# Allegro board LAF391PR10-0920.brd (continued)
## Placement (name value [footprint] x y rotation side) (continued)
PR1240  100K_0402_1%  [R_0402]  56.48 69.47 0 top
PR1241  0_0402_5%  [R0402_0OHM]  44.53 52.02 180 top
PR1242  0_0402_5%  [R0402_0OHM]  48.07 58.22 180 top
PR1243  0_0402_5%  [R0402_0OHM]  57.36 70.34 0 top
PR1244  0_0402_5%  [R0402_0OHM]  50.48 52.99 180 top
PR1245  0_0402_5%  [R0402_0OHM]  40.75 57.83 90 top
PR1246  100K_0402_1%  [R_0402]  53.54 74.39 180 top
PR1247  100K_0402_1%  [R_0402]  55.67 70.34 180 top
PR1248  0_0402_5%  [R_0402]  49.92 71.42 180 top
PR1249  10K_0402_5%  [R_0402]  49.23 73.18 180 top
PR1250  0_0402_5%  [R0402_0OHM]  49.92 72.3 180 top
PR1251  300K_0402_5%  [R_0402]  41.58 72.37 0 top
PR1252  100K_0402_5%  [R_0402]  43.34 72.38 0 top
PR1253  100K_0402_5%  [R_0402]  41.82 78.12 270 top
PR1254  0_0402_5%  [R_0402]  51.52 51.91 270 top
PR1255  150K_0402_1%  [R_0402]  50.87 76.46 0 top
PR1257  0_0402_5%  [R0402_0OHM]  48.07 55.62 180 top
PR1258  0_0402_5%  [R_0402]  48.07 59.1 180 top
PR1259  100K_0402_5%  [R_0402]  49.54 50.93 0 top
PR1260  0_0402_5%  [R_0402]  50.47 52.12 180 top
PR1261  0_0402_5%  [R_0402]  48.07 53.83 180 top
PR1262  100K_0402_5%  [R_0402]  38.75 72.35 90 top
PRP1  100_0804_8P4R_5%  [RP_0804_8P4R]  34.64 19.22 90 top
PT1  PAD~D  [TPC12]  48.05 71.62 0 top
PU1  MC74VHC1G08DFT2G_SC70-5P  [TC7SH08FU_SSOP5]  52.49 88.55 180 bottom
PU2  RT9058-33GX SOT-89 3P LDO  [AP2204R-5P0TRG1_SOT89-3]  52.74 77.67 0 bottom
PU100  -  [SY8288BRAC_QFN20_3X3]  142.03 108.15 270 bottom
PU102  SYV828CRAC QFN 20P PWM  [SY8288CRAC_QFN20_3X3]  43.42 45.54 180 bottom
PU200  -  [SY8210AQVC_QFN19_4X3]  57.23 58.35 90 bottom
PU301  SY8286RAC_QFN20_3X3  [SY8288RAC_QFN20_3X3]  159.22 104.32 0 bottom
PU401  TPS62134CRGT_QFN16_3X3  [SY8057QDC_QFN16_3X3]  173.67 49.7 0 bottom
PU402  TPS62134DRGT_QFN16_3X3  [SY8057QDC_QFN16_3X3]  171.15 98.87 0 bottom
PU501  RT8097ALGE SOT23 6P PWM  [RT8097ALGE_SOT23-6]  173.71 106.15 90 bottom
PU503  AP7361C-FGE-7-01_U-DFN3030-8_3X3  [AP7361C-FGE-7_U-DFN3030-8_3X3]  216.69 14.2 270 top
PU602  ISL95857AHRTZ-T TQFN 40P PWM  [ISL62883CHRTZ-T_TQFN40_5X5-S]  66.57 64.53 0 top
PU610  FDMF3035_PQFN31_5X5  [FDMF3035_PQFN31_5X5-S]  83.71 58.54 180 bottom
PU612  FDMF3035_PQFN31_5X5  [FDMF3035_PQFN31_5X5-S]  64.28 49.41 90 bottom
PU613  FDMF3035_PQFN31_5X5  [FDMF3035_PQFN31_5X5-S]  73.51 76.23 90 bottom
PU614  S IC ISL95808HRZ-TS2778 DFN MOSFET DRIVE  [ISL95808HRZ-TS2378_DFN8_2X2-S]  86.86 87.14 0 bottom
PU901  ISL9538HRTZ-TS2778 TQFN 32P CHARGER  [ISL88738HRTZ-T_TQFN32_4X4]  33.1 45.44 180 bottom
PU903  MC74VHC1G08DFT2G SC70 5P  [TC7SH08FU_SSOP5]  26.98 50.07 270 top
PU1200  MC74VHC1G08DFT2G SC70 5P  [TC7SH08FU_SSOP5]  39.37 76.19 180 top
PU1201  -  [LM393DGKR_VSSOP8]  58.31 77.19 270 top
QC2  -  [DMN65D8LDW-7_SOT363-6]  157.71 66.03 90 top
QC6  -  [L2N7002WT1G_SC-70-3]  246.56 41.7 90 top
QC7  -  [LP2301ALT1G_SOT23-3]  249.69 46.53 180 top
QE2  -  [DMN65D8LDW-7_SOT363-6]  248.34 50.03 270 top
QE3  -  [MMST3904-7-F_SOT323-3]  105.53 58.28 270 top
QE4  -  [MMST3904-7-F_SOT323-3]  105.21 92.92 0 bottom
QE5  -  [MMST3904-7-F_SOT323-3]  210.63 28.76 180 top
QE6  -  [MMST3904-7-F_SOT323-3]  93.07 80.48 270 bottom
QE7  -  [MMST3904-7-F_SOT323-3]  125.99 26.27 270 bottom
QE11  -  [L2N7002WT1G_SC-70-3]  109.66 90.91 180 bottom
QE12  -  [L2N7002WT1G_SC-70-3]  264.16 62.08 0 top
QE15  -  [LP2301ALT1G_SOT23-3]  279.07 66.47 180 top
QE17  -  [L2N7002WT1G_SC-70-3]  259.01 64.12 0 top
QL1  -  [DMN65D8LDW-7_SOT363-6]  270.63 64.57 90 top
QL2  -  [DMN65D8LDW-7_SOT363-6]  270.63 67.43 90 top
QN1  -  [DMN65D8LDW-7_SOT363-6]  249.48 14.78 0 top
QN4  DMN65D8LDW-7_SOT363-6  [DMN66D0LDW-7_SOT363-6]  223.32 33.96 270 top
QN5  DMN65D8LDW-7_SOT363-6  [DMN66D0LDW-7_SOT363-6]  232.58 27.8 0 top
QN6  -  [L2N7002WT1G_SC-70-3]  221.37 30.64 0 top
QN7  -  [L2N7002WT1G_SC-70-3]  218.88 30.65 0 top
QR1  -  [L2N7002WT1G_SC-70-3]  89.97 91.23 180 top
QT1  -  [DMN66D0LDW-7_SOT363-6]  36.15 65.39 270 top
QV1  -  [AO6405_TSOP6]  75.05 98.64 0 top
QV2  -  [L2N7002WT1G_SC-70-3]  77.27 95.74 90 top
QV3  -  [DMN65D8LDW-7_SOT363-6]  20.88 50.21 90 bottom
QV4  -  [L2N7002WT1G_SC-70-3]  19.99 50.41 180 top
QV5  -  [L2N7002WT1G_SC-70-3]  16.31 51.55 180 top
QV7  -  [L2N7002WT1G_SC-70-3]  71.63 108.68 90 top
QV8  -  [LP2301ALT1G_SOT23-3]  65.8 108.92 270 top
QZ1  -  [LP2301ALT1G_SOT23-3]  65.61 96.44 90 top
QZ2  -  [DMN65D8LDW-7_SOT363-6]  282.88 37.31 90 top
QZ3  DDTA114EUA-7-F_SOT323-3  [DDTA144VCA-7-F_SOT23-3]  267.14 29.18 0 top
QZ4  -  [L2N7002WT1G_SC-70-3]  243.64 46.09 180 top
QZ7  -  [DMN65D8LDW-7_SOT363-6]  277.37 70.4 180 top
QZ15  S TR BSS138W 1N SOT-323-3  [L2N7002WT1G_SC-70-3]  223.39 35.75 270 top
R274  0_0603_5%  [R0603_0OHM]  82.92 93.01 0 top
RA3  0_0603_5%  [R0603_0OHM]  265.36 12.75 90 top
RA5  2.2K_0402_5%  [R_0402]  270.54 16.73 0 top
RA6  2.2K_0402_5%  [R_0402]  270.54 17.6 0 top
RA7  16.2_0402_1%  [R_0402]  271.45 15.87 180 top
RA8  16.2_0402_1%  [R_0402]  271.05 14.65 180 top
RA9  33_0402_5%  [R_0402]  261.03 15.6 0 top
RA12  1K_0402_5%  [R_0402]  273.58 22.35 90 top
RA13  1K_0402_5%  [R_0402]  273.58 25.4 270 top
RA14  22_0402_5%  [R_0402]  259.72 19.88 0 top
RA17  33_0402_5%  [R_0402]  254.92 18.31 0 top
RA18  10K_0402_5%  [R_0402]  255.07 24.51 270 top
RA35  0_0402_5%  [R0402_0OHM]  273.61 26.23 90 top
RA36  0_0402_5%  [R0402_0OHM]  276.99 11.98 180 top
RA37  0_0402_5%  [R0402_0OHM]  276.85 19.33 0 bottom
RA44  100K_0402_5%  [R_0402]  272.17 22.84 180 top
RA45  10K_0402_5%  [R_0402]  276.28 21.54 270 top
RA48  0_0402_5%  [R0402_0OHM]  257.36 24.63 270 top
RA50  0_0402_5%  [R_0402]  257.36 21.94 90 top
RA51  10K_0402_5%  [R_0402]  273.61 21.54 270 top
RA53  0_0402_5%  [R_0402]  262.69 25.8 90 bottom
RA57  0_0402_5%  [R0402_0OHM]  263.55 25.8 90 bottom
RA58  10K_0402_5%  [R_0402]  253.8 13.28 0 bottom
RA59  100K_0402_1%  [R_0402]  255.38 26.97 0 top
RA60  200K_0402_1%  [R_0402]  259.14 24.13 180 top
RA61  100K_0402_1%  [R_0402]  265.38 25.8 90 bottom
RA62  100K_0402_5%  [R_0402]  257.22 20.71 0 top
RC1  100K_0402_5%  [R_0402]  134.97 66.8 270 top
RC2  24.9_0402_1%  [R_0402]  111 81.07 180 top
RC3  100_0402_1%  [R_0402]  140.52 80.18 180 top
RC4  200_0402_1%  [R_0402]  151.21 54.36 0 bottom
RC5  121_0402_1%  [R_0402]  129.44 57.01 90 top
RC6  80.6_0402_1%  [R_0402]  128.96 44.5 270 top
RC7  100_0402_1%  [R_0402]  129.98 44.5 270 top
RC10  1K_0402_1%  [R_0402]  162.23 46.97 270 top
RC11  1K_0402_1%  [R_0402]  167.19 49.58 270 bottom
RC12  1K_0402_5%  [R_0402]  147.14 64.45 270 top
RC14  1K_0402_5%  [R_0402]  146.28 64.45 270 top
RC15  1K_0402_5%  [R_0402]  150.36 65.49 90 bottom
RC16  15_0402_5%  [R_0402]  142.3 44.07 0 top
RC17  1K_0402_5%  [R_0402]  148.47 66.43 0 bottom
RC19  499_0402_1%  [R_0402]  155.25 62.92 90 bottom
RC20  499_0402_1%  [R_0402]  154.21 65.55 0 bottom
RC21  8.2K_0402_1%  [R_0402]  154.8 47.35 90 top
RC22  22_0402_5%  [R_0402]  144.07 44.07 0 top
RC23  2.2K_0402_5%  [R_0402]  136.08 64.54 270 top
RC25  4.7K_0402_5%  [R_0402]  151.25 65.49 90 bottom
RC27  8.2K_0402_5%  [R_0402]  140 39.22 180 top
RC28  33_0402_5%  [R_0402]  161.68 49.34 180 bottom
RC29  33_0402_5%  [R_0402]  163.26 52.29 270 bottom
RC30  1K_0402_5%  [R_0402]  168.46 60.37 270 bottom
RC31  1K_0402_5%  [R_0402]  163.63 48.69 90 bottom
RC32  0_0402_5%  [R_0402]  165.67 66.73 325 bottom
RC33  0_0402_5%  [R0402_0OHM]  165.92 65.32 325 bottom
RC34  0_0402_5%  [R0402_0OHM]  167.7 65.33 325 bottom
RC35  0_0402_5%  [R0402_0OHM]  168.08 63.8 325 bottom
RC36  0_0402_5%  [R0402_0OHM]  169.48 64.19 325 bottom
RC37  0_0402_5%  [R0402_0OHM]  159.94 63.28 270 bottom
RC38  0_0402_5%  [R0402_0OHM]  169.99 62.54 325 bottom
RC39  33_0402_5%  [R_0402]  167.57 59.61 180 bottom
RC40  0_0402_5%  [R0402_0OHM]  171.38 62.92 325 bottom
RC41  0_0402_5%  [R0402_0OHM]  173.66 61.25 145 bottom
RC42  0_0402_5%  [R_0402]  160.49 66.09 180 bottom
RC43  33_0402_5%  [R_0402]  167.57 58.72 180 bottom
RC44  113_0402_1%  [R_0402]  149.38 65.53 270 top
RC45  100_0402_1%  [R_0402]  140.9 77.77 270 top
RC46  1M_0402_1%  [R_0402]  120.59 80.06 180 bottom
RC47  10K_0402_5%  [R_0402]  139.29 42.75 270 top
RC48  1K_0402_5%  [R_0402]  143.37 40.69 180 top
RC50  10K_0402_5%  [R_0402]  136.45 40.13 270 top
RC51  10K_0402_5%  [R_0402]  137.31 40.11 0 top
RC52  2.7K_0402_1%  [R_0402]  123.22 83.07 0 top
RC54  10M_0402_5%  [R_0402]  148.35 57.45 90 bottom
RC56  20K_0402_5%  [R_0402]  155.81 42.73 270 top
RC57  20K_0402_5%  [R_0402]  153.8 42.7 270 top
RC59  10K_0402_5%  [R_0402]  137.31 38.33 0 top
RC60  0_0402_5%  [R_0402]  166.17 63.19 90 top
RC62  0_0402_5%  [R0402_0OHM]  160.98 52.79 270 top
RC65  100K_0402_5%  [R_0402]  162.46 54.59 270 top
RC67  1K_0402_5%  [R_0402]  166.4 46.26 90 top
RC68  10K_0402_5%  [R_0402]  164.62 46.26 90 top
RC69  1M_0402_5%  [R_0402]  134.21 44.58 270 top
RC71  1K_0402_5%  [R_0402]  107.5 87.09 90 bottom
RC72  8.2K_0402_5%  [R_0402]  135.1 44.58 270 top
RC73  10K_0402_5%  [R_0402]  149.97 56.93 90 top
RC74  10K_0402_5%  [R_0402]  155.38 45.82 0 top
RC75  10K_0402_5%  [R_0402]  147.65 36.37 0 top
RC77  1K_0402_5%  [R_0402]  99.12 81.02 270 bottom
RC78  60.4_0402_1%  [R_0402]  107.7 86.15 180 bottom
RC79  49.9_0402_1%  [R_0402]  112.6 86.66 90 bottom
RC80  1K_0402_5%  [R_0402]  111.51 84.68 90 bottom
RC81  51_0402_5%  [R_0402]  108.89 80.23 90 top
RC82  100_0402_5%  [R_0402]  110.99 80.04 90 bottom
RC83  1K_0402_5%  [R_0402]  105.59 88.87 90 bottom
RC84  499_0402_1%  [R_0402]  105.59 88.01 270 bottom
RC86  51_0402_5%  [R_0402]  107.17 80.23 90 top
RC87  1K_0402_5%  [R_0402]  108.07 80.04 90 bottom
RC88  49.9_0402_1%  [R_0402]  132.31 44.6 270 top
RC89  49.9_0402_1%  [R_0402]  131.42 44.6 270 top
RC90  49.9_0402_1%  [R_0402]  94.98 63.24 180 top
RC91  49.9_0402_1%  [R_0402]  94.98 64.15 180 top
RC92  33_0402_5%  [R_0402]  135.01 34.32 135 top
RC93  33_0402_5%  [R_0402]  130.32 35.01 90 top
RC94  33_0402_5%  [R_0402]  132.15 35.89 90 top
RC95  33_0402_5%  [R_0402]  131.27 35.01 90 top
RC96  200_0402_1%  [R_0402]  148.49 65.53 270 top
RC109  1K_0402_5%  [R_0402]  97.26 95.42 0 bottom
RC110  10K_0402_1%  [R_0402]  100.64 79.35 90 top
RC112  10K_0402_1%  [R_0402]  100.32 81.14 90 top
RC113  10K_0402_1%  [R_0402]  104.2 88.01 270 bottom
RC114  49.9_0402_1%  [R_0402]  95 65.07 180 top
RC115  1.5K_0402_5%  [R_0402]  115.94 86.9 90 top
RC120  100K_0402_5%  [R_0402]  108.44 87.68 0 bottom
RC121  0_0402_5%  [R_0402]  101.21 93.44 90 bottom
RC122  0_0402_5%  [R_0402]  101.21 92.58 270 bottom
RC123  1K_0402_5%  [R_0402]  98.37 93.52 180 bottom
RC124  1K_0402_5%  [R_0402]  97.45 92.63 0 bottom
RC126  1K_0402_5%  [R_0402]  92.62 94.78 180 bottom
RC128  0_0402_5%  [R_0402]  89.27 93.01 0 bottom
RC129  0_0402_5%  [R_0402]  89.27 93.89 0 bottom
RC130  51_0402_5%  [R_0402]  109.08 80.06 90 bottom
RC131  51_0402_5%  [R_0402]  107.29 98.34 0 top
RC132  150_0402_5%  [R_0402]  91.37 93.89 0 bottom
RC133  1.5K_0402_5%  [R_0402]  89.26 92.12 0 bottom
RC134  51_0402_5%  [R_0402]  107.29 96.95 0 top
RC135  100_0402_5%  [R_0402]  104.45 95.88 270 top
RC136  51_0402_5%  [R_0402]  105.59 80.25 90 top
RC137  3K_0402_5%  [R_0402]  82.99 99.44 270 bottom
RC138  51_0402_5%  [R_0402]  102.61 94.36 270 bottom
RC139  51_0402_5%  [R_0402]  88 94.89 270 bottom
RC140  100_0402_1%  [R_0402]  91.44 65.02 0 top
RC141  100_0402_1%  [R_0402]  91.44 65.91 0 top
RC143  0_0603_5%  [R0603_0OHM]  133.07 82.04 90 top
RC152  56_0402_1%  [R_0402]  103.31 80.06 0 top
RC153  220_0402_5%  [R_0402]  104.2 79.17 180 top
RC157  100_0402_1%  [R_0402]  102.42 79.17 90 top
RC161  100_0402_1%  [R_0402]  92.37 67.17 180 top
RC163  100_0402_1%  [R_0402]  92.37 68.04 180 top
RC165  100_0402_1%  [R_0402]  124.72 58.53 180 top
RC166  100_0402_1%  [R_0402]  127.18 76.81 90 top
RC167  100_0402_1%  [R_0402]  127.66 57.78 0 top
RC168  100_0402_1%  [R_0402]  126.29 77.72 270 top
RC169  0_0603_5%  [R0603_0OHM]  134.91 79.12 90 bottom
RC170  0_0402_5%  [R0402_0OHM]  128.03 81.76 270 bottom
RC171  0_0402_5%  [R0402_0OHM]  127.18 82.8 180 bottom
RC173  0_0402_5%  [R0402_0OHM]  127.15 81.76 270 bottom
RC175  2.2K_0402_5%  [R_0402]  146.66 67.27 0 top
RC176  2.2K_0402_5%  [R_0402]  154.91 75.18 270 top
RC177  2.2K_0402_5%  [R_0402]  156.32 75.18 270 top
RC178  2.2K_0402_5%  [R_0402]  146.66 66.38 0 top
RC183  8.2K_0402_5%  [R_0402]  153.28 53.7 90 top
RC184  8.2K_0402_5%  [R_0402]  152.15 54.49 90 top
RC186  4.7K_0402_5%  [R_0402]  150.88 56.94 90 top
RC187  4.7K_0402_5%  [R_0402]  136.83 34.94 315 top
RC189  10K_0402_5%  [R_0402]  138.4 42.75 270 top
RC190  10K_0402_5%  [R_0402]  140 40.11 180 top
RC211  0_0402_5%  [R_0402]  157.84 52.12 180 top
RC212  0_0402_5%  [R0402_0OHM]  155.11 58.7 270 bottom
RC214  0_0402_5%  [R_0402]  147.32 56.54 0 top
RC215  0_0402_5%  [R_0402]  145.62 36.37 0 top
RC216  0_0603_1%  [R0603_0OHM]  93.76 92.75 90 bottom
RC217  0_0402_5%  [R_0402]  92.29 93.01 180 bottom
RC218  150_0402_5%  [R_0402]  92.39 91.23 180 bottom
RC219  10K_0402_5%  [R_0402]  92.39 92.12 180 bottom
RC220  100K_0402_1%  [R_0402]  143.82 36.37 0 top
RC221  0_0402_5%  [R0402_0OHM]  288.66 92.26 270 bottom
RC222  1K_0402_5%  [R_0402]  288.66 93.25 90 bottom
RC223  1K_0402_5%  [R_0402]  135.98 35.28 135 top
RC224  1K_0402_5%  [R_0402]  146.3 87.58 180 bottom
RC225  8.2K_0402_5%  [R_0402]  148.14 89.45 180 bottom
RC227  8.2K_0402_5%  [R_0402]  149.03 89.45 0 bottom
RC228  0_0402_5%  [R0402_0OHM]  107.25 100.7 270 top
RC229  0_0402_5%  [R0402_0OHM]  105.72 95.88 270 top
RC230  0_0402_5%  [R0402_0OHM]  103.18 95.88 270 top
RC231  0_0402_5%  [R0402_0OHM]  117.2 52.94 180 top
RC234  0_0402_5%  [R_0402]  147.17 60.68 180 top
RC235  0_0402_5%  [R0402_0OHM]  134.99 64.52 270 top
RC237  10K_0402_5%  [R_0402]  151.76 57.83 90 top
RC239  0_0402_5%  [R_0402]  100.14 93.43 90 bottom
RC240  0_0402_5%  [R_0402]  99.25 93.43 90 bottom
RC241  1.5K_0402_5%  [R_0402]  96.15 94.76 270 bottom
RC243  10K_0402_5%  [R_0402]  167.8 46.26 90 top
RC244  0_0402_5%  [R0402_0OHM]  160.09 52.79 270 top
RC267  10K_0402_5%  [R_0402]  153.28 55.46 90 bottom
RC268  10K_0402_5%  [R_0402]  153.67 54.58 270 bottom
RC272  10K_0402_5%  [R_0402]  144.72 83.96 180 top
RC278  10K_0402_5%  [R_0402]  150.31 65.83 90 top
RC279  10K_0402_5%  [R_0402]  153.08 60.02 270 top
RC282  100K_0402_5%  [R_0402]  151.2 54.94 90 top
RC283  10K_0402_5%  [R_0402]  150.54 59.65 0 bottom
RC287  100K_0402_5%  [R_0402]  153.12 61.5 0 bottom
RC288  10K_0402_5%  [R_0402]  144.84 80.95 90 top
RC290  0_0402_5%  [R0402_0OHM]  150.8 88.31 270 bottom
RC291  10K_0402_5%  [R_0402]  145.39 88.47 0 bottom
RC292  10K_0402_5%  [R_0402]  152.79 59.99 0 bottom
RC295  0_0402_5%  [R0402_0OHM]  121.45 80.06 0 bottom
RC296  0_0402_5%  [R0402_0OHM]  148.35 56.61 270 bottom
RC297  0_0402_5%  [R_0402]  116.26 81.89 90 top
RC298  0_0402_5%  [R_0402]  115.26 81.89 90 top
RC299  0_0603_5%  [R0603_0OHM]  149.78 69.38 180 bottom
RC300  0_0402_5%  [R0402_0OHM]  137.02 80.01 270 bottom
RC301  0_0402_5%  [R0402_0OHM]  149.39 67.32 180 bottom
RC302  0_0402_5%  [R0402_0OHM]  136.01 80.01 270 bottom
RC303  0_0402_5%  [R0402_0OHM]  131.32 84.18 180 bottom
RC304  0_0402_5%  [R0402_0OHM]  147.17 61.58 180 top
RC305  0_0402_5%  [R0402_0OHM]  171.9 57.67 180 top
RC306  0_0402_5%  [R0402_0OHM]  171.9 58.53 180 top
RC307  0_0402_5%  [R0402_0OHM]  148.92 62.42 270 top
RC308  0_0402_5%  [R0402_0OHM]  148.06 62.42 270 top
RC309  0_0603_5%  [R0603_0OHM]  140.26 80.5 270 bottom
RC310  0_0603_5%  [R0603_0OHM]  134.87 78.79 90 top
RC311  10K_0402_5%  [R_0402]  132.82 55.98 90 top
RC313  0_0402_5%  [R_0402]  148.43 62.43 0 bottom
RC316  1K_0402_5%  [R_0402]  164.52 49.58 270 bottom
RC317  150K_0402_5%  [R_0402]  149.09 56.93 90 top
RC318  2.2K_0402_5%  [R_0402]  156.29 68.47 180 top
RC319  2.2K_0402_5%  [R_0402]  158.88 68.72 180 top
RC323  10K_0402_5%  [R_0402]  140.77 36.24 0 top
RC324  59_0402_1%  [R_0402]  123.75 76.17 90 top
RC325  0_0402_5%  [R0402_0OHM]  165.26 64.78 270 top
RC328  0_0402_5%  [R0402_0OHM]  112.6 84.41 90 bottom
RC330  49.9K_0402_1%  [R_0402]  131.75 93.06 90 top
RC331  49.9K_0402_1%  [R_0402]  130.8 93.06 90 top
RC337  10K_0402_5%  [R_0402]  146.47 59.79 0 top
RC338  1K_0402_5%  [R_0402]  149.04 59.91 270 top
RC344  10K_0402_5%  [R_0402]  165.51 46.26 90 top
RC345  100K_0402_5%  [R_0402]  143.31 80.69 90 top
RC346  10K_0402_5%  [R_0402]  145.85 80.95 90 top
RC347  499_0402_1%  [R_0402]  152.12 63.81 0 bottom
RC348  499_0402_1%  [R_0402]  152.12 64.7 0 bottom
RC349  100_0402_1%  [R_0402]  155.93 40.64 270 top
RC362  1K_0402_5%  [R_0402]  161.75 69.29 90 bottom
RC363  1K_0402_5%  [R_0402]  162.64 69.29 90 bottom
RC366  15_0402_5%  [R_0402]  169.23 40.46 0 top
RC367  15_0402_5%  [R_0402]  169.26 38.6 0 top
RC368  15_0402_5%  [R_0402]  169.26 39.52 0 top
RC369  15_0402_5%  [R_0402]  169.26 37.72 0 top
RC370  10K_0402_5%  [R_0402]  152.39 55.46 90 bottom
RC371  10K_0402_5%  [R_0402]  151.27 67.31 180 bottom
RC372  10K_0402_5%  [R_0402]  152.16 67.32 270 bottom
RC373  0_0402_5%  [R0402_0OHM]  138.42 43.61 90 top
RC374  0_0402_5%  [R0402_0OHM]  140.2 42.75 270 top
RC376  0_0402_5%  [R0402_0OHM]  137.84 37.26 315 top
RC377  0_0402_5%  [R0402_0OHM]  136.45 42.72 270 top
RC378  0_0402_5%  [R0402_0OHM]  141.22 41.51 270 top
RC387  10K_0402_5%  [R_0402]  133.66 52.24 0 top
RC400  10K_0402_5%  [R_0402]  154.03 67.32 270 bottom
RC401  10K_0402_5%  [R_0402]  153.14 67.32 270 bottom
RC402  49.9K_0402_1%  [R_0402]  131.75 91.63 270 top
RC403  49.9K_0402_1%  [R_0402]  130.8 91.63 270 top
RC404  10K_0402_5%  [R_0402]  148.48 66.37 90 top
RC405  100K_0402_5%  [R_0402]  151.26 61.49 0 bottom
RC407  33_0402_5%  [R_0402]  162.74 48.69 90 bottom
RC408  33_0402_5%  [R_0402]  165.41 49.58 270 bottom
RC409  33_0402_5%  [R_0402]  166.3 49.58 270 bottom
RC410  33_0402_5%  [R_0402]  159.05 63.28 270 bottom
RC411  10K_0402_5%  [R_0402]  168.69 46.26 90 top
RC413  10K_0402_5%  [R_0402]  151.21 65.85 90 top
RC414  10K_0402_5%  [R_0402]  146.51 43.49 0 top
RC417  33_0402_5%  [R_0402]  147.34 79.05 90 bottom
RC418  33_0402_5%  [R_0402]  146.44 79.05 90 bottom
RC419  33_0402_5%  [R_0402]  120.59 79.17 180 bottom
RC420  33_0402_5%  [R_0402]  122.37 79.17 180 bottom
RC421  1M_0402_1%  [R_0402]  147.69 80.85 0 bottom
RC422  33_0402_5%  [R_0402]  146.81 80.85 180 bottom
RC431  100K_0402_5%  [R_0402]  249.61 40.94 0 top
RC432  499K_0402_1%  [R_0402]  250.49 42.74 180 top
RC433  49.9K_0402_1%  [R_0402]  247.2 43.4 180 top
RC436  0_0402_5%  [R_0402]  99.88 77.77 270 top
RC437  0_0402_5%  [R_0402]  110.09 80.18 0 top
RC438  0_0402_5%  [R_0402]  111.38 57.96 180 top
RC439  0_0402_5%  [R0402_0OHM]  247.2 44.34 90 top
RC440  0_0402_5%  [R_0402]  246.31 44.37 90 top
RC441  0_0402_5%  [R0402_0OHM]  259.33 36.89 270 top
RC442  0_0402_5%  [R_0402]  258.44 36.89 270 top
RC443  0_0402_5%  [R_0402]  141.67 38.02 180 top
RC444  0_0402_5%  [R0402_0OHM]  154.49 45.56 90 top
RC445  0_0402_5%  [R0402_0OHM]  249.81 39.11 90 top
RC551  1K_0402_5%  [R_0402]  134.79 57.87 180 top
RC553  10K_0402_5%  [R_0402]  154.91 68.02 270 bottom
RC554  10K_0402_5%  [R_0402]  155.93 68.64 0 bottom
RC555  10K_0402_5%  [R_0402]  159.58 68.64 270 bottom
RC556  10K_0402_5%  [R_0402]  158.67 68.64 180 bottom
RC560  0_0402_5%  [R_0402]  149.69 44.48 180 top
RC561  0_0402_5%  [R_0402]  147.01 44.48 0 top
RD4  0_0402_5%  [R_0402]  119.22 14.81 270 top
RD5  0_0402_5%  [R0402_0OHM]  118.33 13.9 90 top
RD6  0_0402_5%  [R_0402]  119.22 12.12 90 top
RD7  0_0402_5%  [R0402_0OHM]  118.33 13.03 270 top
RD8  0_0402_5%  [R_0402]  96.08 11.38 180 top
RD9  0_0402_5%  [R0402_0OHM]  95.16 12.27 0 top
RD10  0_0603_5%  [R0603_0OHM]  119.83 18.86 90 top
RD11  470_0402_1%  [R_0402]  51.86 11.81 180 top
RD12  0_0402_5%  [R0402_0OHM]  50.38 12.7 0 top
RD14  1K_0402_5%  [R_0402]  83.53 11.43 90 top
RD15  1K_0402_1%  [R_0402]  90.99 14.27 270 top
RD16  1K_0402_1%  [R_0402]  91.85 13.36 90 top
RD17  2_0402_1%  [R_0402]  93.33 11.36 90 top
RD18  24.9_0402_1%  [R_0402]  94.25 13.13 90 top
RD19  100K_0402_5%  [R_0402]  50.28 13.74 90 top
RD20  0_0402_5%  [R_0402]  206.45 16.98 270 bottom
RD21  0_0402_5%  [R0402_0OHM]  207.31 16.98 270 bottom
RD22  0_0402_5%  [R0402_0OHM]  205.57 16.98 270 bottom
RD23  0_0402_5%  [R_0402]  204.7 16.06 90 bottom
RD24  0_0402_5%  [R_0402]  176.87 12.27 270 top
RD25  0_0402_5%  [R0402_0OHM]  175.99 11.36 90 top
RD26  0_0603_5%  [R0603_0OHM]  198.48 23.05 270 top
RD27  1K_0402_5%  [R_0402]  165.88 11.36 90 top
RD28  1K_0402_1%  [R_0402]  46.41 13.97 270 top
RD29  1K_0402_1%  [R_0402]  44.63 13.05 90 top
RD30  2_0402_1%  [R_0402]  45.52 13.05 90 top
RD31  24.9_0402_1%  [R_0402]  44.63 15.74 270 top
RE5  10K_0402_5%  [R_0402]  271.56 49.58 0 top
RE8  100K_0402_5%  [R_0402]  272.47 41.96 270 top
RE10  100K_0402_5%  [R_0402]  257.79 42.12 270 top
RE11  100K_0402_5%  [R_0402]  256.51 53.22 180 top
RE12  100K_0402_5%  [R_0402]  261.01 32.79 90 top
RE20  100K_0402_5%  [R_0402]  256.6 52.17 180 top
RE21  10K_0402_5%  [R_0402]  268.77 58.9 90 top
RE25  100K_0402_5%  [R_0402]  271.71 38.02 180 top
RE26  10_0402_5%  [R_0402]  271.71 35.73 90 top
RE30  0_0402_5%  [R0402_0OHM]  233.02 13.88 270 top
RE31  100K_0402_5%  [R_0402]  277.63 55.74 180 top
RE32  0_0402_5%  [R0402_0OHM]  249.58 54 0 top
RE33  1K_0402_5%  [R_0402]  276.71 53.96 0 top
RE35  10K_0402_5%  [R_0402]  269.8 41.96 270 top
RE37  2.2K_0402_5%  [R_0402]  259.52 42.12 270 top
RE38  10K_0402_5%  [R_0402]  271.6 44.01 0 top
RE43  2.2K_0402_5%  [R_0402]  258.66 42.12 270 top
RE48  10K_0402_5%  [R_0402]  178.69 91.36 270 bottom
RE51  10K_0402_5%  [R_0402]  179.67 91.36 270 bottom
RE55  100K_0402_5%  [R_0402]  257.05 55.27 180 top
RE56  10K_0402_5%  [R_0402]  254.99 42.85 0 top
RE57  1K_0402_5%  [R_0402]  247.43 51.66 180 top
RE58  100K_0402_5%  [R_0402]  247.43 52.55 180 top
RE59  0_0402_5%  [R0402_0OHM]  277.63 50.21 180 top
RE60  43_0402_5%  [R_0402]  271.6 46.01 0 top
RE63  100K_0402_5%  [R_0402]  274.01 53.86 0 top
RE64  300_0402_5%  [R_0402]  256.51 43.98 180 top
RE65  100_0402_1%  [R_0402]  274.01 51.71 0 top
RE67  10K_0402_5%  [R_0402]  247.43 50.77 180 top
RE68  100K_0402_5%  [R_0402]  250.5 51.35 180 top
RE69  8.2K_0402_5%  [R_0402]  106.23 94.66 270 bottom
RE70  2.2K_0402_5%  [R_0402]  106.56 88.87 90 bottom
RE71  10_0402_1%  [R_0402]  237.23 11.3 270 top
RE72  10K_0402_5%  [R_0402]  234.42 10.38 90 top
RE73  10K_0402_5%  [R_0402]  231.58 10.38 90 top
RE74  10K_0402_5%  [R_0402]  233.52 10.38 90 top
RE75  100K_0402_5%  [R_0402]  232.55 10.38 90 top
RE77  1.58K_0402_1%  [R_0402]  272.98 61.9 180 top
RE79  4.3K_0402_5%  [R_0402]  274.3 46.4 0 top
RE83  100K_0402_5%  [R_0402]  274.3 47.34 0 top
RE84  100K_0402_5%  [R_0402]  274.02 49.04 90 top
RE85  100K_0402_5%  [R_0402]  274.91 49.04 90 top
RE86  10K_0402_5%  [R_0402]  231.61 13.88 270 top
RE90  0_0402_5%  [R0402_0OHM]  107.5 89.79 270 bottom
RE91  100K_0402_5%  [R_0402]  271.6 54.89 0 top
RE92  100K_0402_5%  [R_0402]  254.29 54.91 180 top
RE93  100K_0201_5%  [R_0201]  265.23 59.13 0 top
RE94  75_0402_5%  [R_0402]  264.98 63.17 90 top
RE95  100K_0402_5%  [R_0402]  267.14 40.76 270 top
RE274  0_0402_5%  [R_0402]  271.58 41.04 90 top
RE275  0_0402_5%  [R0402_0OHM]  270.71 41.04 90 top
RE280  0_0402_5%  [R_0402]  277.4 38.81 180 top
RE288  100_0402_5%  [R_0402]  274.3 48.21 0 top
RE290  0_0402_5%  [R0402_0OHM]  260.35 56.56 180 top
RE292  0_0402_5%  [R_0402]  275.66 38.81 180 top
RE300  130K_0402_5%  [R_0402]  276.8 46.3 0 top
RE301  10K_0402_5%  [R_0402]  271.6 54 0 top
RE302  2.2K_0402_5%  [R_0402]  250.5 53.13 180 top
RE303  2.2K_0402_5%  [R_0402]  250.5 52.24 180 top
RE304  0_0402_5%  [R_0402]  276.43 33.96 180 top
RE306  0_0402_5%  [R_0402]  230.5 13.88 270 top
RE308  0_0402_5%  [R_0402]  272.51 45.12 180 top
RE312  300_0402_5%  [R_0402]  254.31 50.47 180 top
RE313  10K_0402_5%  [R_0402]  254.31 51.35 180 top
RE314  100_0402_1%  [R_0402]  250.55 51.74 270 bottom
RE318  0_0402_5%  [R0402_0OHM]  256.51 48.68 180 top
RE324  100K_0402_5%  [R_0402]  256.51 54.15 180 top
RE340  10K_0402_5%  [R_0402]  252.99 43 180 top
RE342  10K_0402_5%  [R_0402]  260.25 38.02 270 top
RE343  240K_0402_5%  [R_0402]  253.22 49.2 0 top
RE349  43K_0402_1%  [R_0402]  259.35 38.32 90 top
RE350  33_0402_5%  [R_0402]  255.58 36.75 90 top
RE361  49.9K_0402_1%  [R_0402]  254.29 53.16 180 top
RE362  100K_0402_5%  [R_0402]  254.29 54.05 180 top
RE365  100K_0402_5%  [R_0402]  271.56 50.67 0 top
RE375  0_0402_5%  [R_0402]  255.07 40.31 90 top
RE505  100K_0402_5%  [R_0402]  266.76 64.7 270 top
RE507  100K_0402_5%  [R_0402]  246.64 52.75 270 bottom
RE508  100K_0402_5%  [R_0402]  247.53 52.75 270 bottom
RE524  2.2K_0402_5%  [R_0402]  261.45 60.68 180 top
RE525  2.2K_0402_5%  [R_0402]  266.5 41.32 270 bottom
RE526  10K_0402_5%  [R_0402]  280.34 55.93 90 top
RE532  4.7K_0402_5%  [R_0402]  276.52 42.78 0 bottom
RE536  0_0402_5%  [R0402_0OHM]  277.68 56.69 180 top
RE539  100_0402_5%  [R_0402]  265.49 40.42 90 bottom
RE541  100K_0402_5%  [R_0402]  275.65 65.48 270 top
RE543  1M_0402_5%  [R_0402]  276.53 65.45 270 top
RE546  10K_0402_5%  [R_0402]  276.66 59.99 180 top
RE547  100K_0402_5%  [R_0402]  262.18 39.62 270 top
RE548  0_0402_5%  [R0402_0OHM]  254.06 42.95 90 top
RE549  100K_0402_5%  [R_0402]  256.34 41.27 270 top
RE550  100K_0402_5%  [R_0402]  256.85 42.13 90 top
RE551  0_0402_5%  [R_0402]  276.86 57.96 180 top
RE552  0_0402_5%  [R0402_0OHM]  224.5 36.39 270 top
RE560  0_0402_5%  [R_0402]  250.55 37.18 90 bottom
RE561  100K_0402_5%  [R_0402]  258.47 38.32 90 top
RE565  0_0402_5%  [R_0402]  262.4 61.11 270 top
RI13  10K_0402_5%  [R_0402]  276.41 32.89 180 top
RI14  22.1K_0402_1%  [R_0402]  279.66 29.51 90 top
RI27  0_0402_5%  [R_0402-NPM]  253.61 32.23 0 bottom
RI28  0_0402_5%  [R_0402-NPM]  253.61 31.34 0 bottom
RI29  0_0402_5%  [R_0402-NPM]  253.61 34.02 0 bottom
RI30  0_0402_5%  [R_0402-NPM]  253.61 33.13 0 bottom
RI47  0_0402_5%  [R_0402-NPM]  252.67 28.04 0 top
RI48  0_0402_5%  [R_0402-NPM]  252.65 28.93 0 top
RI49  0_0402_5%  [R_0402-NPM]  205.85 38.34 0 bottom
RI50  0_0402_5%  [R_0402-NPM]  205.85 37.45 0 bottom
RL1  10K_0402_5%  [R_0402]  251.9 69.58 180 top
RL2  10K_0402_5%  [R_0402]  251.9 68.69 180 top
RL3  0_0402_5%  [R0402_0OHM]  267.01 68.96 270 top
RL4  4.7K_0402_5%  [R_0402]  260.41 67.71 270 top
RL5  10K_0402_5%  [R_0402]  263.87 63.17 90 top
RL6  4.7K_0402_5%  [R_0402]  261.36 67.71 270 top
RL7  0_0402_5%  [R0402_0OHM]  262.11 63.17 0 top
RL8  0_0603_5%  [R0603_0OHM]  263.14 65.32 0 top
RL9  10K_0402_5%  [R_0402]  263.02 64.05 180 top
RL11  1M_0402_5%  [R_0402]  262.12 71.81 90 top
RL12  1K_0402_5%  [R_0402]  252.15 73.71 270 top
RL13  3.01K_0402_1%  [R_0402]  262.49 79.14 0 top
RL14  150_0402_5%  [R_0402]  269.93 63.17 0 top
RL15  75_0402_1%  [R_0402]  268.1 95.04 180 top
RL16  75_0402_1%  [R_0402]  268.1 91.99 180 top
RL17  75_0402_1%  [R_0402]  268.1 89.07 180 top
RL18  75_0402_1%  [R_0402]  268.1 86.03 180 top
RL19  150_0402_5%  [R_0402]  271.12 71.42 0 top
RL20  150_0402_5%  [R_0402]  271.12 70.28 0 top
RL29  1M_0402_5%  [R_0402]  267.64 64.76 90 top
RL30  1M_0402_5%  [R_0402]  271.64 68.35 270 top
RL34  0_0402_5%  [R0402_0OHM]  263.01 72.73 270 top
RL70  10K_0402_5%  [R_0402]  140.77 37.13 0 top
RL71  2.2_0603_5%  [R_0603]  260.91 81.86 90 top
RL72  2.2_0603_5%  [R_0603]  259.64 81.86 90 top
RL73  2.2_0603_5%  [R_0603]  258.37 81.86 90 top
RL74  2.2_0603_5%  [R_0603]  257.1 81.86 90 top
RL75  2.2_0603_5%  [R_0603]  255.83 81.86 90 top
RL76  2.2_0603_5%  [R_0603]  254.56 81.86 90 top
RL77  2.2_0603_5%  [R_0603]  253.29 81.86 90 top
RL78  2.2_0603_5%  [R_0603]  252.02 81.86 90 top
RN1  100K_0402_5%  [R_0402]  249.9 12.04 90 top
RN2  100K_0402_5%  [R_0402]  247.52 16.2 0 top
RN3  10K_0402_5%  [R_0402]  221.35 18.91 180 top
RN4  10K_0402_5%  [R_0402]  239.03 16.67 270 top
RN5  10K_0402_5%  [R_0402]  239.91 15.76 90 top
RN6  4.7K_0402_5%  [R_0402]  220.53 21.31 0 top
RN7  4.7K_0402_5%  [R_0402]  220.53 20.43 0 top
RN8  4.7K_0402_5%  [R_0402]  221.44 22.26 180 top
RN9  4.7K_0402_5%  [R_0402]  220.53 23.21 0 top
RN10  4.7K_0402_5%  [R_0402]  228.38 19.73 0 top
RN11  4.7K_0402_5%  [R_0402]  229.29 18.84 180 top
RN12  4.7K_0402_5%  [R_0402]  229.29 23.29 180 top
RN13  4.7K_0402_5%  [R_0402]  229.29 22.4 180 top
RN14  4.7K_0402_5%  [R_0402]  222.84 24.19 180 top
RN15  7.87K_0402_1%  [R_0402]  221.92 25.07 0 top
RN16  4.7K_0402_5%  [R_0402]  229.29 17.06 180 top
RN17  4.7K_0402_5%  [R_0402]  229.29 17.95 180 top
RN18  4.7K_0402_5%  [R_0402]  226.24 15.21 90 top
RN19  4.7K_0402_5%  [R_0402]  225.35 16.13 270 top
RN20  4.7K_0402_5%  [R_0402]  229.29 20.62 180 top
RN21  4.7K_0402_5%  [R_0402]  228.38 21.51 0 top
RN25  10K_0402_5%  [R_0402]  243.39 21.76 0 top
RN26  10K_0402_5%  [R_0402]  243.77 19.07 90 top
RN27  10K_0402_5%  [R_0402]  248.31 18.21 0 top
RN28  10K_0402_5%  [R_0402]  245.51 16.7 90 top
RN30  4.99K_0402_1%  [R_0402]  246.46 19.99 270 top
RN31  4.99K_0402_1%  [R_0402]  236.39 18.41 270 top
RN37  10K_0402_5%  [R_0402]  255.36 9.72 0 bottom
RN38  10K_0402_5%  [R_0402]  244.28 20.87 180 top
RN39  10K_0402_5%  [R_0402]  244.66 19.99 270 top
RN40  10K_0402_5%  [R_0402]  250.02 19.99 270 top
RN41  10K_0402_5%  [R_0402]  245.55 19.99 270 top
RN42  10K_0402_5%  [R_0402]  227.59 28.62 180 top
RN43  10K_0402_5%  [R_0402]  227.59 29.51 180 top
RN44  10K_0402_5%  [R_0402]  231.53 31.29 180 top
RN49  10K_0402_5%  [R_0402]  247.39 17.29 90 top
RN50  10K_0402_5%  [R_0402]  248.01 26.97 0 top
RN51  10K_0402_5%  [R_0402]  251.9 20.21 90 top
RN52  10K_0402_5%  [R_0402]  247.4 19.99 270 top
RN53  10K_0402_5%  [R_0402]  248.92 27.86 180 top
RN54  10K_0402_5%  [R_0402]  251.9 22.02 90 top
RN55  10K_0402_5%  [R_0402]  231.69 18.84 0 top
RN56  10K_0402_5%  [R_0402]  233.47 17.5 90 top
RN57  10K_0402_5%  [R_0402]  239.73 19.94 90 top
RN58  10K_0402_5%  [R_0402]  234.36 17.5 90 top
RN59  10K_0402_5%  [R_0402]  232.6 19.86 180 top
RN60  10K_0402_5%  [R_0402]  232.2 17.9 270 top
RN61  10K_0402_5%  [R_0402]  240.63 20.85 270 top
RN62  10K_0402_5%  [R_0402]  235.37 18.41 270 top
RN63  10K_0402_5%  [R_0402]  235.01 28.57 270 top
RN64  10K_0402_5%  [R_0402]  235.89 28.57 270 top
RN65  10K_0402_5%  [R_0402]  221.44 32.55 0 top
RN69  10K_0402_5%  [R_0402]  238.42 17.5 90 top
RN70  10K_0402_5%  [R_0402]  235.89 26.79 270 top
RN71  10K_0402_5%  [R_0402]  240.62 22.27 180 top
RN72  10K_0402_5%  [R_0402]  237.41 18.41 270 top
RN73  10K_0402_5%  [R_0402]  237.04 25.88 90 top
RN74  10K_0402_5%  [R_0402]  239.7 23.67 0 top
RN77  0_0402_5%  [R0402_0OHM]  270.7 13.13 180 bottom
RN78  0_0402_5%  [R0402_0OHM]  270.7 12.24 180 bottom
RN81  0_0402_5%  [R0402_0OHM]  273.99 12.23 90 bottom
RN82  0_0402_5%  [R0402_0OHM]  274.86 12.23 90 bottom
RN99  0_0402_5%  [R0402_0OHM]  252.1 9.52 180 bottom
RN100  0_0402_5%  [R_0402]  275.77 12.23 90 bottom
RN101  0_0402_5%  [R_0402]  260.13 33.7 270 top
RN171  100K_0402_5%  [R_0402]  233.33 31.14 0 top
RN174  10K_0402_5%  [R_0402]  229.68 31.29 180 top
RN176  10K_0402_5%  [R_0402]  225.76 29.51 180 top
RN179  10K_0402_5%  [R_0402]  225.77 28.62 180 top
RN182  0_0402_5%  [R_0402]  223.52 31.48 0 top
RN183  100K_0402_5%  [R_0402]  226.66 33.42 270 top
RN184  0_0402_5%  [R_0402]  232.34 25.88 90 top
RN185  100K_0402_5%  [R_0402]  233.23 26.79 270 top
RN186  0_0402_5%  [R0402_0OHM]  231.45 25.88 90 top
RN187  0_0402_5%  [R_0402]  230.56 28.57 270 top
RN188  100K_0402_5%  [R_0402]  231.45 28.57 270 top
RN189  0_0402_5%  [R0402_0OHM]  230.56 25.88 90 top
RN192  0_0402_5%  [R0402_0OHM]  227.59 34.34 180 top
RN223  0_0402_5%  [R0402_0OHM]  222.36 33.44 180 top
RN224  0_0402_5%  [R0402_0OHM]  235.01 26.79 270 top
RN225  0_0402_5%  [R0402_0OHM]  234.12 26.79 270 top
RN226  4.7K_0402_5%  [R_0402]  220.27 32.69 270 top
RN227  0_0402_5%  [R_0402]  220.68 24.96 270 top
RN228  4.7K_0402_5%  [R_0402]  218.88 32.69 270 top
RN229  0_0402_5%  [R_0402]  243.59 24.43 180 top
RN230  0_0402_5%  [R_0402]  239.93 25.02 135 top
RPC1  33_0804_8P4R_5%  [RP_0804_8P4R]  167.57 51.08 90 bottom
RPC3  10K_8P4R_5%  [RP_0804_8P4R]  143.24 79.48 90 bottom
RPC4  10K_8P4R_5%  [RP_0804_8P4R]  155.12 71.17 0 top
RPE7  10K_8P4R_5%  [RP_0804_8P4R]  237.04 13.83 270 top
RPE9  100K_0804_8P4R_5%  [RP_0804_8P4R]  270.52 36.32 270 top
RPE10  100K_0804_8P4R_5%  [RP_0804_8P4R]  265.73 36.18 270 top
RPE11  100K_0804_8P4R_5%  [RP_0804_8P4R]  254.09 45.61 180 top
RPE12  2.2K_0804_8P4R_5%  [RP_0804_8P4R]  268.76 40.66 270 bottom
RR3  10K_0402_5%  [R_0402]  84.08 93.14 180 bottom
RR4  6.2K_0402_1%  [R_0402]  76.75 89.79 270 bottom
RR5  0_0402_5%  [R0402_0OHM]  77.2 98.52 90 bottom
RR6  0_0402_5%  [R0402_0OHM]  79.01 98.52 90 bottom
RR7  0_0402_5%  [R0402_0OHM]  79.89 98.52 90 bottom
RR8  0_0402_5%  [R0402_0OHM]  80.78 98.52 90 bottom
RR9  0_0402_5%  [R0402_0OHM]  75.45 97.1 180 bottom
RR10  0_0402_5%  [R0402_0OHM]  75.45 97.99 180 bottom
RR19  10K_0402_5%  [R_0402]  83.16 92.25 0 bottom
RT50  3.3K_0402_5%  [R_0402]  44.48 68.25 0 bottom
RT51  3.3K_0402_5%  [R_0402]  54.23 71.27 0 bottom
RT52  3.3K_0402_5%  [R_0402]  56.58 70.07 0 bottom
RT53  3.3K_0402_5%  [R_0402]  56.93 70.96 180 bottom
RT54  0_0402_5%  [R0402_0OHM]  50.35 71.27 90 bottom
RT55  0_0402_5%  [R0402_0OHM]  52.13 71.37 180 bottom
RT56  0_0402_5%  [R0402_0OHM]  57.5 69.19 180 bottom
RT57  0_0402_5%  [R0402_0OHM]  34.93 63.6 180 top
RT58  0_0402_5%  [R0402_0OHM]  36.75 66.43 0 top
RT59  0_0402_5%  [R0402_0OHM]  37.57 63.07 180 top
RT60  0_0402_5%  [R0402_0OHM]  34.04 53.97 90 top
RT63  0_0402_5%  [R0402_0OHM]  34.01 68.22 0 top
RT64  0_0402_5%  [R_0402]  29.87 53.46 180 top
RT65  0_0402_5%  [R_0402]  29.89 54.35 180 top
RT66  3.3K_0402_5%  [R_0402]  31.63 61.81 0 top
RT67  3.3K_0402_5%  [R_0402]  31.63 62.7 0 top
RT68  10K_0402_5%  [R_0402]  33.18 54.89 270 top
RT69  0_0402_5%  [R_0402]  31.79 65.83 0 top
RT70  0_0402_5%  [R0402_0OHM]  31.79 66.66 0 top
RT71  1M_0402_5%  [R_0402]  29.9 55.27 180 top
RT72  0_0402_5%  [R0402_0OHM]  25.71 54.91 180 top
RT73  0_0402_5%  [R0402_0OHM]  29.87 57.08 270 top
RT74  0_0402_5%  [R0402_0OHM]  28 57.1 270 top
RT75  0_0402_5%  [R_0402]  25.71 55.85 180 top
RT76  10K_0402_1%  [R_0402]  23.3 53.56 180 top
RT81  100K_0402_5%  [R_0402]  34.01 67.33 0 top
RT82  1M_0402_5%  [R_0402]  31.79 68.31 0 top
RT83  0_0402_5%  [R0402_0OHM]  32.71 67.42 180 top
RT84  0_0402_5%  [R_0402]  34.01 64.49 0 top
RT85  0_0402_5%  [R_0402]  34.01 65.38 0 top
RT86  1M_0402_5%  [R_0402]  28.88 57.1 270 top
RT87  0_0402_5%  [R_0402]  24.13 77.11 270 bottom
RT88  0_0402_5%  [R_0402]  21.81 76.12 0 bottom
RT89  0_0402_5%  [R0402_0OHM]  21.34 62.19 0 top
RT90  0_0402_5%  [R_0402]  22.25 63.08 180 top
RT92  0_0402_5%  [R0402_0OHM]  21.34 63.97 0 top
RT93  0_0402_5%  [R0402_0OHM]  21.39 65.17 0 top
RT95  100K_0402_5%  [R_0402]  21.31 66.9 90 top
RT96  100K_0402_5%  [R_0402]  23.47 66.9 90 top
RT97  0_0402_5%  [R_0402]  24.79 54.05 0 top
RT98  0_0402_5%  [R_0402]  26.52 54.05 0 top
RT99  0_0402_5%  [R0402_0OHM]  26.52 54.91 0 top
RT100  15K_0402_1%  [R_0402]  26.18 66.88 90 top
RT101  100K_0402_5%  [R_0402]  34.01 62.66 0 top
RT103  0_0402_5%  [R_0402]  23.3 55.34 180 top
RT104  0_0402_5%  [R0402_0OHM]  22.53 58.01 90 top
RT105  0_0402_5%  [R0402_0OHM]  22.53 56.23 90 top
RT106  10K_0402_5%  [R_0402]  29.23 67.79 270 top
RT107  10K_0402_5%  [R_0402]  30.11 67.79 270 top
RT108  0_0402_5%  [R_0402]  19.33 59.48 0 top
RT109  0_0402_5%  [R_0402]  19.33 60.37 0 top
RT110  0_0402_5%  [R_0402]  27.11 56.18 90 top
RT111  100K_0402_5%  [R_0402]  18.62 65.88 90 top
RT120  0_0402_5%  [R0402_0OHM]  14.69 73.15 180 bottom
RT121  0_0402_5%  [R0402_0OHM]  14.69 74.04 180 bottom
RT122  0_0402_5%  [R0402_0OHM]  13.77 71.75 0 top
RT123  0_0402_5%  [R0402_0OHM]  13.77 72.64 0 top
RT130  100K_0402_5%  [R_0402]  30.28 80.46 90 top
RT131  100K_0402_5%  [R_0402]  27.61 80.46 90 top
RT132  0_0402_5%  [R_0402]  25.84 80.49 90 top
RT133  0_0402_5%  [R_0402]  26.73 80.49 90 top
RT135  1K_0402_5%  [R_0402]  20.83 69.62 180 top
RT136  1K_0402_5%  [R_0402]  20.83 70.51 180 top
RT137  1K_0402_5%  [R_0402]  31.4 74.34 270 bottom
RT138  1K_0402_5%  [R_0402]  32.29 74.34 270 bottom
RT139  1K_0402_5%  [R_0402]  33.08 75.18 90 bottom
RT140  1K_0402_5%  [R_0402]  31.3 75.18 90 bottom
RT141  1K_0402_5%  [R_0402]  20.12 76.07 270 top
RT142  1K_0402_5%  [R_0402]  21.01 76.07 270 top
RT143  1K_0402_5%  [R_0402]  21.77 73.66 270 top
RT144  1K_0402_5%  [R_0402]  20.88 73.66 270 top
RT145  1K_0402_5%  [R_0402]  33.08 77.85 270 bottom
RT246  0_0402_5%  [R_0402]  24.29 69.69 90 top
RT247  1K_0402_5%  [R_0402]  22.61 71.4 180 top
RT248  1K_0402_5%  [R_0402]  22.61 70.51 180 top
RT300  1K_0402_5%  [R_0402]  31.35 77.85 270 bottom
RT301  20K_0402_5%  [R_0402]  32.21 77.85 270 bottom
RT302  20K_0402_5%  [R_0402]  33.18 74.34 270 bottom
RT303  20K_0402_5%  [R_0402]  22.61 69.62 180 top
RT304  20K_0402_5%  [R_0402]  19.99 73.66 270 top
RT305  20K_0402_5%  [R_0402]  20.83 71.4 180 top
RT306  20K_0402_5%  [R_0402]  32.19 75.18 90 bottom
RT307  20K_0402_5%  [R_0402]  21.9 76.07 270 top
RT308  4.7K_0402_5%  [R_0402]  24.05 77.87 90 top
RT339  0_0402_5%  [R_0402]  31.82 55.03 270 top
RT375  0_0402_5%  [R_0402]  20.12 65.02 270 top
RT376  0_0402_5%  [R_0402]  19.16 64.11 90 top
RT377  43K_0402_1%  [R_0402]  23.3 54.45 180 top
RT378  10K_0402_5%  [R_0402]  31.55 69.21 0 top
RT379  10K_0402_5%  [R_0402]  31.55 70.15 0 top
RT380  0_0402_5%  [R0402_0OHM]  26.86 75.48 180 bottom
RT393  100K_0402_5%  [R_0402]  16.83 62.78 180 top
RT397  0_0603_5%  [R_0603]  20.25 77.77 90 top
RT398  0_0603_5%  [R0603_0OHM]  12.18 66.15 90 bottom
RT405  1M_0402_5%  [R_0402]  17.76 75.48 0 top
RT406  1M_0402_5%  [R_0402]  20.38 68.32 270 top
RT407  10K_0402_5%  [R_0402]  17.76 77.26 0 top
RT410  4.7K_0402_5%  [R_0402]  33.79 81.42 180 top
RT411  4.7K_0402_5%  [R_0402]  33.79 80.54 180 top
RT412  4.7K_0402_5%  [R_0402]  32.52 81.83 180 bottom
RT413  4.7K_0402_5%  [R_0402]  30.66 81.38 90 bottom
RT414  2M_0402_5%  [R_0402]  24.19 79.13 180 bottom
RT415  2M_0402_5%  [R_0402]  24.19 78.24 180 bottom
RT416  4.7K_0402_5%  [R_0402]  21.3 78.89 270 top
RT417  0_0402_5%  [R_0402]  18.67 74.6 180 top
RT418  0_0402_5%  [R_0402]  17.76 76.37 0 top
RV1  4.7K_0402_5%  [R_0402]  68.88 94.53 180 top
RV2  4.7K_0402_5%  [R_0402]  68.97 93.14 180 top
RV3  100K_0402_5%  [R_0402]  74.68 91.89 270 top
RV4  270K_0402_5%  [R_0402]  78.29 100.68 90 top
RV5  47K_0402_5%  [R_0402]  78.29 99.69 270 top
RV6  10K_0402_5%  [R_0402]  70.53 107.84 90 top
RV7  100K_0402_5%  [R_0402]  68.05 92.25 0 top
RV8  10K_0402_5%  [R_0402]  61.62 94.87 90 top
RV10  470_0402_1%  [R_0402]  19.92 42.85 0 top
RV11  470_0402_1%  [R_0402]  19.92 43.73 0 top
RV12  470_0402_1%  [R_0402]  19.92 46.47 0 top
RV13  470_0402_1%  [R_0402]  19.92 47.35 0 top
RV14  470_0402_1%  [R_0402]  19.92 44.69 0 top
RV15  470_0402_1%  [R_0402]  19.92 45.58 0 top
RV16  470_0402_1%  [R_0402]  19.92 48.24 0 top
RV17  470_0402_1%  [R_0402]  19.92 49.13 0 top
RV18  10K_0402_5%  [R_0402]  19.66 53.51 0 top
RV19  10K_0402_5%  [R_0402]  15.47 50.34 0 top
RV20  1M_0402_5%  [R_0402]  15.85 54.66 0 top
RV21  20K_0402_5%  [R_0402]  18.09 52.04 90 top
RV22  2.2K_0402_5%  [R_0402]  23.8 50.67 270 bottom
RV23  2.2K_0402_5%  [R_0402]  19.74 51.41 90 bottom
RV24  5.6_0402_5%  [R_0402]  18.17 42.85 180 bottom
RV25  5.6_0402_5%  [R_0402]  18.17 43.73 180 bottom
RV26  200_0402_5%  [R_0402]  16.06 43.75 270 bottom
RV27  5.6_0402_5%  [R_0402]  18.17 46.47 180 bottom
RV28  5.6_0402_5%  [R_0402]  18.17 47.35 180 bottom
RV29  200_0402_5%  [R_0402]  16.06 47.37 270 bottom
RV30  5.6_0402_5%  [R_0402]  18.17 44.69 180 bottom
RV31  5.6_0402_5%  [R_0402]  18.17 45.58 180 bottom
RV32  200_0402_5%  [R_0402]  16.06 45.59 270 bottom
RV33  5.6_0402_5%  [R_0402]  18.17 48.24 180 bottom
RV34  5.6_0402_5%  [R_0402]  18.17 49.13 180 bottom
RV35  200_0402_5%  [R_0402]  16.06 49.15 270 bottom
RV70  100K_0402_5%  [R_0402]  174.86 83.61 0 top
RV72  100K_0402_5%  [R_0402]  174.86 85.64 0 top
RV73  1M_0402_5%  [R_0402]  165.54 87.47 90 top
RV75  1M_0402_5%  [R_0402]  169.6 87.47 90 top
RV76  100K_0402_5%  [R_0402]  174.86 82.47 0 top
RV78  100K_0402_5%  [R_0402]  174.86 84.5 0 top
RV79  4.7K_0402_5%  [R_0402]  157.99 86.22 180 top
RV80  4.7K_0402_5%  [R_0402]  160.15 86.22 180 top
RV81  4.7K_0402_5%  [R_0402]  157.99 85.26 180 top
RV82  4.7K_0402_5%  [R_0402]  160.15 85.26 180 top
RV83  4.7K_0402_5%  [R_0402]  157.99 84.31 180 top
RV84  4.7K_0402_5%  [R_0402]  160.15 84.31 180 top
RV85  4.7K_0402_5%  [R_0402]  157.99 83.36 180 top
RV86  4.7K_0402_5%  [R_0402]  160.15 83.36 180 top
RV87  4.7K_0402_5%  [R_0402]  160.15 80.45 180 top
RV88  4.7K_0402_5%  [R_0402]  160.15 81.37 180 top
RV89  4.7K_0402_5%  [R_0402]  164.65 76.83 270 top
RV90  4.7K_0402_5%  [R_0402]  165.54 76.83 270 top
RV91  4.7K_0402_5%  [R_0402]  168.71 76.83 270 top
RV92  4.7K_0402_5%  [R_0402]  169.6 76.83 270 top
RV93  4.7K_0402_5%  [R_0402]  161.22 78.86 270 top
RV94  4.7K_0402_5%  [R_0402]  162.11 78.86 270 top
RV95  4.7K_0402_5%  [R_0402]  160.15 79.56 180 top
RV96  4.7K_0402_5%  [R_0402]  160.15 78.65 180 top
RV97  4.99K_0402_1%  [R_0402]  172.7 79.85 0 top
RV102  100K_0402_5%  [R_0402]  279.84 46.35 180 top
RV106  4.7K_0402_5%  [R_0402]  279.84 47.29 180 top
RV107  4.7K_0402_5%  [R_0402]  276.8 47.54 0 top
RV116  75_0402_1%  [R_0402]  282.12 60.73 90 top
RV117  75_0402_1%  [R_0402]  282.12 59.61 270 top
RV118  75_0402_1%  [R_0402]  282.12 56.41 90 top
RV119  2.2K_0402_5%  [R_0402]  289.01 51.48 180 bottom
RV120  2.2K_0402_5%  [R_0402]  288.98 48.81 180 bottom
RV121  1K_0402_5%  [R_0402]  287.96 52.37 180 top
RV122  1K_0402_5%  [R_0402]  287.96 53.64 180 top
RV123  4.7K_0402_5%  [R_0402]  288.99 46.91 180 top
RV124  4.7K_0402_5%  [R_0402]  288.99 46.02 180 top
RV323  0_0402_5%  [R0402_0OHM]  74.73 109.47 270 top
RV324  0_0402_5%  [R_0402]  74.73 106.78 90 top
RV326  100K_0402_5%  [R_0402]  74.73 111.25 270 top
RV400  0_0402_5%  [R_0402]  69.65 107.36 90 top
RV620  4.7K_0402_5%  [R_0402]  288.99 47.8 180 top
RV622  4.7K_0402_5%  [R_0402]  285.98 47.85 90 bottom
RV650  75_0402_1%  [R_0402]  285.14 53.6 0 top
RV651  75_0402_1%  [R_0402]  285.14 52.71 0 top
RZ8  2.2K_0402_5%  [R_0402]  258.73 13.15 0 top
RZ9  2.2K_0402_5%  [R_0402]  257.84 13.84 270 top
RZ10  100K_0402_5%  [R_0402]  253.04 13.78 270 top
RZ18  4.7K_0402_5%  [R_0402]  203.23 23.9 270 top
RZ19  4.7K_0402_5%  [R_0402]  204.17 23.9 270 top
RZ20  2.2K_0402_5%  [R_0402]  205.31 26.03 270 top
RZ21  2.2K_0402_5%  [R_0402]  206.3 25.7 270 top
RZ22  0_0402_5%  [R_0402]  203.23 25.12 90 top
RZ23  0_0402_5%  [R_0402]  204.17 25.12 90 top
RZ25  150_0402_5%  [R_0402]  268.75 28.19 270 top
RZ26  0_0402_5%  [R0402_0OHM]  205.31 23.9 270 top
RZ28  330_0402_5%  [R_0402]  273.68 13.01 270 top
RZ29  0_0402_5%  [R0402_0OHM]  206.49 23.9 270 top
RZ32  330_0402_5%  [R_0402]  276.15 71.37 0 top
RZ38  100K_0402_5%  [R_0402]  216.92 35.71 0 top
RZ40  100K_0402_5%  [R_0402]  230.94 37.77 0 top
RZ43  47K_0402_5%  [R_0402]  260.28 39.66 270 bottom
RZ56  0_0402_5%  [R0402_0OHM]  219.38 26.49 0 top
RZ58  33_0402_5%  [R_0402]  153.55 63.67 180 top
RZ59  33_0402_5%  [R_0402]  160.62 68.21 180 top
RZ60  33_0402_5%  [R_0402]  163.77 63.88 90 top
RZ61  0_0402_5%  [R0402_0OHM]  161.61 66.4 180 top
RZ62  10K_0402_5%  [R_0402]  153.55 61.51 180 top
RZ63  33_0402_5%  [R_0402]  166.17 65.85 270 top
RZ64  0_0402_5%  [R0402_0OHM]  179.62 61.2 180 top
RZ65  0_0402_5%  [R_0402]  179.62 62.21 180 top
RZ69  10K_0402_5%  [R_0402]  162.41 63.62 180 top
RZ70  0_0402_5%  [R_0402]  217.83 34.82 180 top
RZ71  0_0402_5%  [R_0402]  217.83 33.93 180 top
RZ76  0_0402_5%  [R_0402]  267.95 34.67 270 top
RZ77  0_0402_5%  [R_0402]  267.06 34.67 270 top
RZ78  0_0402_5%  [R_0402]  214.05 25.7 0 top
RZ79  0_0402_5%  [R_0402]  212.15 25.7 0 top
RZ80  0_0402_5%  [R_0402]  216.84 24.13 0 top
RZ81  0_0402_5%  [R_0402]  216.84 23.21 0 top
RZ85  0_0402_5%  [R0402_0OHM]  264.29 12.11 180 top
RZ87  0_0402_5%  [R0402_0OHM]  252.02 12.87 270 top
RZ89  0_0402_5%  [R0402_0OHM]  158.22 53.39 0 top
RZ90  0.01_1206_1%  [R_1206-NPM]  73.46 98.75 180 top
RZ93  0.01_1206_1%  [R_1206-NPM]  68.32 86.28 0 top
RZ96  0.01_1206_1%  [R_1206-NPM]  211.43 37 90 top
RZ99  0.01_1206_1%  [R_1206-NPM]  248.09 15.48 270 bottom
RZ102  0.01_1206_1%  [R_1206-NPM]  243.84 12.01 270 top
RZ112  0_0402_5%  [R0402_0OHM]  156.94 66.14 180 bottom
RZ114  0_0402_5%  [R_0402]  254.26 10.44 270 bottom
RZ116  10K_0402_5%  [R_0402]  205.44 20.82 90 top
RZ117  10K_0402_5%  [R_0402]  206.43 20.82 90 top
RZ119  0_0402_5%  [R_0402]  125.45 38.78 0 top
RZ120  0_0402_5%  [R0402_0OHM]  130.27 33.55 180 top
RZ128  0_0201_5%  [R_0201]  274.07 40.42 0 bottom
RZ129  0_0201_5%  [R_0201]  274.07 39.72 0 bottom
RZ130  0_0201_5%  [R_0201]  275.52 39.08 0 bottom
RZ132  0_0402_5%  [R_0402]  276.66 51.75 0 top
RZ151  0_0603_5%  [R_0603]  128.62 85.79 270 bottom
RZ320  0_0402_5%  [R_0402]  136.37 88.62 270 bottom
RZ326  0_0402_5%  [R_0402]  264.42 26.72 270 bottom
RZ334  51_0402_5%  [R_0402]  116.27 98.03 0 top
RZ335  15K_0402_5%  [R_0402]  118.8 108.56 90 top
RZ345  0_0402_5%  [R0402_0OHM]  236.55 39.29 90 top
RZ346  0_0402_5%  [R0402_0OHM]  204.6 27.07 180 top
RZ347  0_0402_5%  [R0402_0OHM]  201.65 27.07 0 top
RZ361  150_0402_5%  [R_0402]  269.85 32.18 270 top
RZ362  10K_0402_5%  [R_0402]  158.68 66.98 180 bottom
RZ363  0_0402_5%  [R_0402]  157.79 66.09 0 bottom
RZ364  100_0402_5%  [R_0402]  261.6 12.11 0 top
RZ365  0_0402_5%  [R0402_0OHM]  157.66 63.85 90 top
RZ366  0_0402_5%  [R_0402]  156.77 63.85 90 top
RZ367  0_0402_5%  [R_0402]  158.22 54.28 0 top
RZ368  0_0402_5%  [R0402_0OHM]  156.95 52.98 90 top
RZ369  0_0402_5%  [R_0402]  156.9 55.62 270 top
RZ370  100_0603_5%  [R_0603]  242.56 44.75 0 top
RZ380  0_0402_5%  [R_0402]  62.48 100.52 0 top
RZ518  10K_0402_5%  [R_0402]  225.4 35.48 90 top
SW1  SS3-CMFTQR9_3P  [SW_SS3-CMFTQR9_3P]  291.44 89.87 0 bottom
SW3  SKRBAAE010_4P  [SW_SKRBAAE010_4P]  295.36 92.97 270 top
T1  PAD~D  [TPC12]  113.59 70.4 0 top
T2  PAD~D  [TPC12]  114.38 69.29 0 top
T3  PAD~D  [TPC12]  107.23 53.82 0 top
T4  PAD~D  [TPC12]  106.82 41.93 0 top
T5  PAD~D  [TPC12]  109.55 56.69 0 top
T6  PAD~D  [TPC12]  109.59 55.23 0 top
T9  PAD~D  [TPC12]  100.64 82.6 180 bottom
T10  PAD~D  [TPC12]  110.27 76.77 180 bottom
T11  PAD~D  [TPC12]  109.08 78.66 180 bottom
T12  PAD~D  [TPC12]  90.53 44.78 0 top
T13  PAD~D  [TPC12]  91.8 44.67 0 top
T14  PAD~D  [TPC12]  133.23 58.92 0 top
T15  PAD~D  [TPC12]  134.79 58.84 0 top
T16  PAD~D  [TPC12]  93.12 44.57 0 top
T17  PAD~D  [TPC12]  96.85 44.6 0 top
T18  PAD~D  [TPC12]  143.81 59.53 180 bottom
T19  PAD~D  [TPC12]  143.02 76.91 180 bottom
T50  PAD~D  [TPC12]  91.71 18.11 0 top
T51  PAD~D  [TPC12]  94.4 15.79 0 top
T54  PAD~D  [TPC12]  175.45 13.67 0 top
T55  PAD~D  [TPC12]  174.92 15.06 0 top
T87  PAD~D  [TPC12]  289.74 56.82 180 bottom
T88  PAD~D  [TPC12]  251.1 71.92 0 top
T89  PAD~D  [TPC12]  252.44 70.54 0 top
T113  PAD~D  [TPC12]  94.34 44.22 0 top
T114  PAD~D  [TPC12]  95.56 44.67 0 top
T115  PAD~D  [TPC12]  134.23 53.26 0 top
T120  PAD~D  [TPC12]  134.01 66.75 0 top
T122  PAD~D  [TPC12]  122.86 76.37 0 top
T123  PAD~D  [TPC12]  122.38 56.59 0 top
T126  PAD~D  [TPC12]  144.26 50.28 180 bottom
T127  PAD~D  [TPC12]  144.26 48.88 180 bottom
T128  PAD~D  [TPC12]  146.98 54.83 180 bottom
T129  PAD~D  [TPC12]  144.86 55.44 180 bottom
T130  PAD~D  [TPC12]  146.6 42.39 90 top
T132  PAD~D  [TPC12]  98.61 44.57 0 top
T141  PAD~D  [TPC12]  257.52 51.9 0 top
T142  PAD~D  [TPC12]  268.91 42.59 0 top
T143  PAD~D  [TPC12]  266.09 41.21 0 top
T144  PAD~D  [TPC12]  257.55 44.42 0 top
T147  PAD~D  [TPC12]  264.34 42.34 180 bottom
T204  PAD~D  [TPC12]  163.25 77.54 0 top
T219  PAD~D  [TPC12]  35.82 66.9 90 top
T220  PAD~D  [TPC12]  34.42 66.34 90 top
T223  PAD~D  [TPC12]  163.48 75.97 0 top
T224  PAD~D  [TPC12]  166.81 75.87 0 top
T225  PAD~D  [TPC12]  275.4 26.82 180 bottom
T258  PAD~D  [TPC12]  145.08 43.05 0 top
T262  PAD~D  [TPC12]  268.91 43.48 180 bottom
T264  PAD~D  [TPC12]  270.59 50.59 270 top
T268  PAD~D  [TPC12]  136.2 54.86 0 top
T281  PAD~D  [TPC12]  112.96 80.31 0 top
T282  PAD~D  [TPC12]  112.96 81.58 0 top
T283  PAD~D  [TPC12]  161.27 60.05 90 top
TL1  350UH_IH-160  [TAIMA_IH-160_24P]  258.98 86.03 90 bottom
UA1  ALC3254-VA3-CG_MQFN48_6X6  [ALC3254-CG_MQFN48_6X6]  261.93 22.25 0 top
UC1  KBL-RU42_BGA1356  [KBL-RU42_BGA_1356P-T]  140.6 73.65 0 bottom
UC5  W25Q128JVSIQ_SO8  [W25Q128FVSIQ_SO8]  161.45 61.35 0 bottom
UC6  W25Q128JVSIQ_SO8  [W25Q128FVSIQ_SO8]  155.61 56.27 0 bottom
UC7  TC7SH08FU_SSOP5~D  [TC7SH08FU_SSOP5]  160.16 53.85 0 top
UC8  74CBTLV3126BQ_DHVQFN14_2P5X3  [74CBTLV3126BQ_DHVQFN14_2P5X3-S]  102.67 99.11 0 top
UC12  -  [74AHC1G09GW_TSSOP5]  149.41 88.31 270 bottom
UD1  -  [74AUP1G07GW_TSSOP5]  49.49 29.82 180 top
UE1  MEC5105_WFBGA169_11X11  [MEC5105_WFBGA_169P]  259.22 54.13 0 top
UE3  TC7SH08FU_SSOP5~D  [TC7SH08FU_SSOP5]  274.09 36.26 270 top
UE4  -  [74AUP1G07GW_TSSOP5]  274.37 44.13 270 top
UE5  TC7SH08FU_SSOP5~D  [TC7SH08FU_SSOP5]  274.67 41.13 270 top
UE6  -  [74AUP1G07GW_TSSOP5]  253.77 40.51 90 top
UI1  -  [SY6288D20AAC_SOT23-5]  26.8 18.55 270 top
UI3  -  [SLGC55544CVTR_TQFN16_3X3]  277.41 31.31 180 top
UL1  WGI219LM-QREF- A0_QFN48_6X6~D  [WGI217LM-QPN9-A2_QFN48_6X6-S]  259.62 71.12 90 top
UL2  TC7SH08FU_SSOP5~D  [TC7SH08FU_SSOP5]  273.93 64.64 90 top
UN4  PS8558BTQFN24GTR2-A_TQFN24_4X4  [PS8558BTQFN24_TQFN24_4X4-S]  245.8 24.68 0 top
UN5  PS8558BTQFN24GTR2-A_TQFN24_4X4  [PS8558BTQFN24_TQFN24_4X4-S]  234.09 23.33 0 top
UN7  PI3EQX6741STZDEX_TQFN20_4X4  [PI3EQX6741STZDEX_TQFN20_4X4-S]  225.97 22.41 270 top
UR1  RTS5242-GR_QFN32_4X4  [RTS5242-GR_QFN32_4X4-S]  80.77 91.7 90 bottom
UT5  TPS65982DC_BGA96  [TPS65982_BGA_96P]  29.69 64.31 270 top
UT6  GD25Q80CSIGR_SO8  [W25Q80DVSSIG_SO8]  54.54 69.9 270 bottom
UT7  AP2112K-3.3TRG1_SOT23-5  [AP2112K-3P3TRG1_SOT23-5]  17.5 65.14 90 top
UT8  AP2204R-5.0TRG1_SOT89-3  [AP2204R-5P0TRG1_SOT89-3]  11.51 59.61 0 top
UT9  TUSB546A_QFN40_4X6  [TUSB546_QFN40_4X6]  26.4 72.43 90 top
UV2  -  [AP2330W-7_SC59-3]  18.53 51.35 90 bottom
UV4  -  [AP2330W-7_SC59-3]  285.75 42.97 270 bottom
UV6  RTD2166-CG_QFN32_4X4  [RTD2166-CG_QFN32_4X4-S]  282.37 46.76 90 top
UV7  PS8338BQFN60GTR-A0_QFN60_5X9  [PS8338BQFN60GTR-A0_QFN60_5X9-S]  162.79 80.68 0 top
